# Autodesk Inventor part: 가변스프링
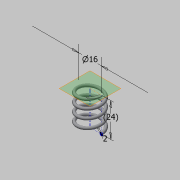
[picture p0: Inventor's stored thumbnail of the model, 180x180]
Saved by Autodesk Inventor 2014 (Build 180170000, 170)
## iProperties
Created: 2015-04
Part Number: 가변스프링
Material: 강철, 탄소
Document SubType Name: Modeling
Designer: Administrator
Mass: 4.78743 g
Surface Area: 12.5262 cm^2
Volume: 0.608313 cm^3
Density: 7.87 g/cm^3
Appearance: 반연마
Author: Administrator
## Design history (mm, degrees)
sketch "스케치1"
  geometry: L1 (0, 0)-(8, 0); L2 (8, 0)-(8, 11.5); L3 (8, 11.5)-(0, 11.5); L4 (0, 11.5)-(0, 0); C1 r 1 at (8, 0)
  constraints: 8 end point, 2 parallel, 1 centre point, 1 coincident, 1 horizontal, 1 perpendicular
  dimensions: "d0" = 16 diameter of L2 L4; "d1" = 11.50049 distance between parallel lines of L1 L3 (derived); "d2" = 2 diameter of C1
feature "코일1" pitch "d3" = 10; turns "d5" = 4; dims "d4" = 11.50049 (= d1), "d6" = 0, angle "d7" = 90 deg, angle "d8" = 90 deg, "d9" = 0, "d10" = 0
sketch "스케치2"
  geometry: L1 (-9, 0)-(-7, 0) reference; 1 further point
  constraints: 1 horizontal alignment
extrude "돌출1" cut sketch "스케치2" stored distance "d11" = 10; taper "d12" = 0 deg
node "작업 평면1"
sketch "스케치3"
  geometry: L1 (9, 0)-(7, 0) reference; 1 further point
  constraints: 1 horizontal alignment
extrude "돌출2" cut sketch "스케치3" stored distance "d13" = 10; taper "d14" = 0 deg
node "솔리드1"
node "절단 모서리 투영1"
node "절단 모서리 투영2"
